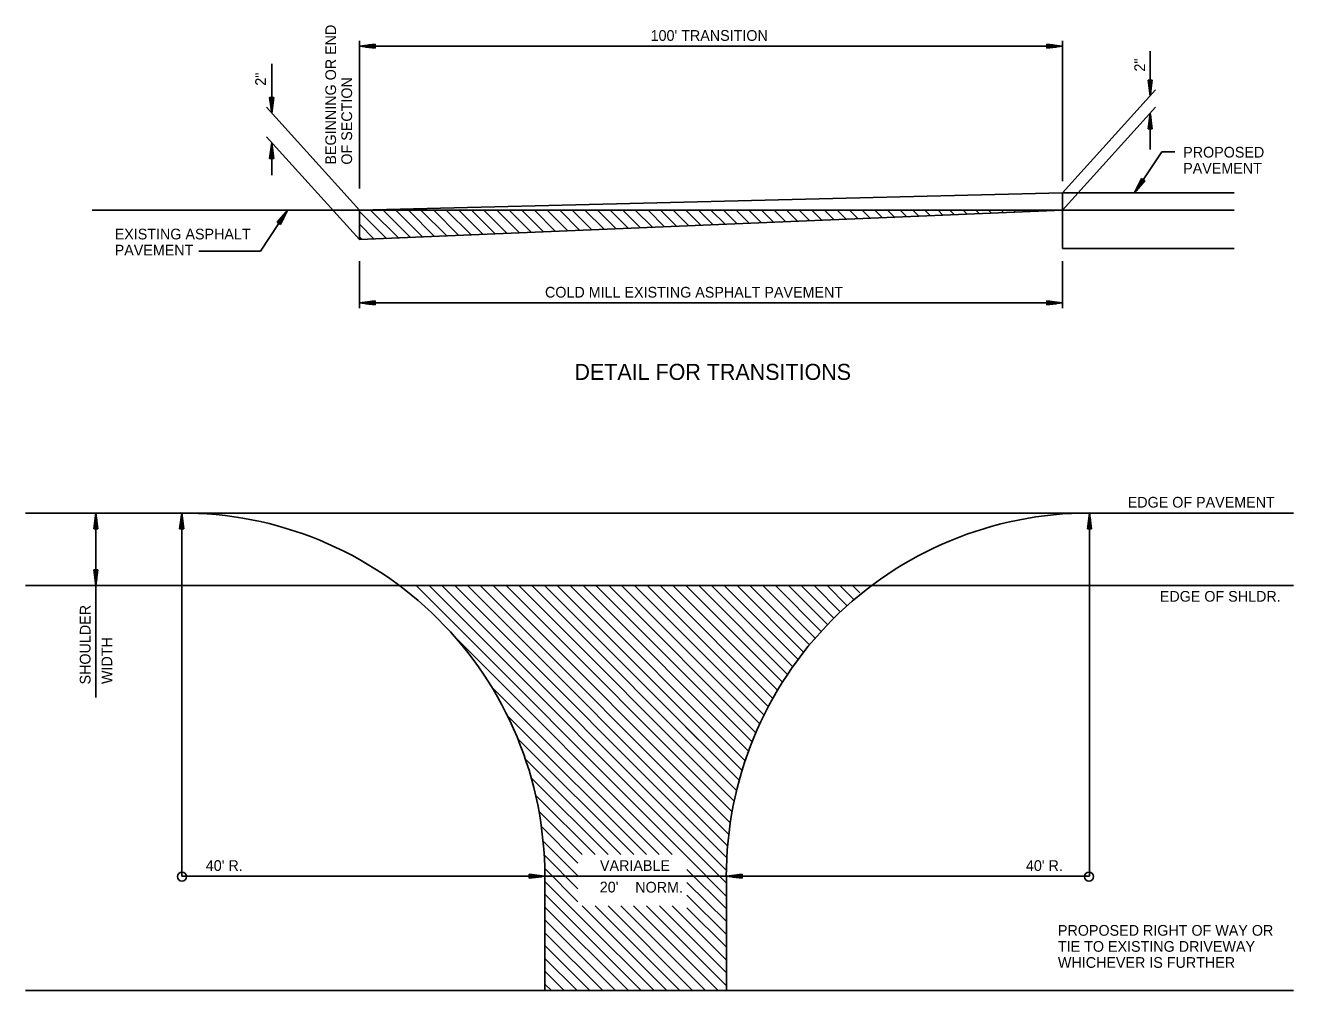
# Model space of a CAD drawing. Extents: x 836 to 5683, y -463 to 1545.
# Drawn here: x 836 to 1548, y 733 to 1274 of the extents above; entities that cross this region are included whole.
import ezdxf

# ---------------------------------------------------------------- set-up
doc = ezdxf.new("R2010")
doc.units = 0
for name, color, linetype in [('R_Border', 7, 'Continuous'), ('R_Draft', 7, 'Continuous'), ('R_Grid', 7, 'Continuous'), ('STAMP_PP', 7, 'Continuous')]:
    doc.layers.add(name, color=color, linetype=linetype)

msp = doc.modelspace()

# ---------------------------------------------------------------- linework, layer by layer
at = {"layer": 'R_Draft'}
for p, q in [((1039.08, 1154.14), (1023.83, 1169.39)), ((1045.98, 1154.29), (1030.08, 1170.19)), ((1052.43, 1154.93), (1037.08, 1170.19)), ((1059.2, 1155.21), (1044.23, 1170.19)), ((1065.97, 1155.49), (1051.33, 1170.19)), ((1072.78, 1155.78), (1058.28, 1170.19)), ((1079.55, 1156.06), (1065.43, 1170.19)), ((1086.36, 1156.34), (1072.43, 1170.19)), ((1093.13, 1156.63), (1079.58, 1170.19)), ((1099.95, 1156.91), (1086.68, 1170.19)), ((1106.71, 1157.19), (1093.63, 1170.19)), ((1113.49, 1157.48), (1100.78, 1170.19)), ((1120.29, 1157.76), (1107.78, 1170.19)), ((1127.07, 1158.04), (1114.93, 1170.19)), ((1133.84, 1158.33), (1122.03, 1170.19)), ((1140.65, 1158.61), (1129.08, 1170.19)), ((1147.42, 1158.89), (1136.13, 1170.19)), ((1154.22, 1159.18), (1143.13, 1170.19)), ((1161, 1159.46), (1150.28, 1170.19)), ((1167.78, 1159.74), (1157.38, 1170.19)), ((1174.59, 1160.03), (1164.43, 1170.19)), ((1181.4, 1160.31), (1171.53, 1170.19)), ((1188.15, 1160.59), (1178.48, 1170.19)), ((1194.94, 1160.88), (1185.63, 1170.19)), ((1201.69, 1161.16), (1192.63, 1170.19)), ((1208.52, 1161.44), (1199.78, 1170.19)), ((1215.34, 1161.73), (1206.88, 1170.19)), ((1222.1, 1162.01), (1213.93, 1170.19)), ((1228.84, 1162.29), (1220.88, 1170.19)), ((1235.61, 1162.57), (1227.93, 1170.19)), ((1242.45, 1162.86), (1235.13, 1170.19)), ((1249.27, 1163.14), (1242.23, 1170.19)), ((1256.04, 1163.42), (1249.28, 1170.19)), ((1262.85, 1163.71), (1256.38, 1170.19)), ((1269.5, 1163.99), (1263.28, 1170.19)), ((1276.39, 1164.27), (1270.48, 1170.19)), ((1283.2, 1164.56), (1277.58, 1170.19)), ((1289.97, 1164.84), (1284.63, 1170.19)), ((1296.79, 1165.12), (1291.73, 1170.19)), ((1303.41, 1165.4), (1298.58, 1170.19)), ((1310.22, 1165.69), (1305.68, 1170.19)), ((1317.14, 1165.97), (1312.93, 1170.19)), ((1323.9, 1166.26), (1319.98, 1170.19)), ((1330.72, 1166.54), (1327.08, 1170.19)), ((1337.49, 1166.82), (1334.13, 1170.19)), ((1344.04, 1167.1), (1340.88, 1170.19)), ((1351.07, 1167.39), (1348.28, 1170.19)), ((1357.53, 1167.66), (1354.93, 1170.19)), ((1364.65, 1167.96), (1362.43, 1170.19)), ((1371.42, 1168.24), (1369.48, 1170.19)), ((1378.24, 1168.52), (1376.58, 1170.19)), ((1385.01, 1168.81), (1383.63, 1170.19)), ((1391.78, 1169.09), (1390.68, 1170.19)), ((1398.59, 1169.37), (1397.78, 1170.19)), ((1405.21, 1169.65), (1404.68, 1170.19)), ((1411.89, 1169.93), (1411.63, 1170.19)), ((1032.13, 1153.99), (1023.83, 1162.29)), ((1025.33, 1153.74), (1023.83, 1155.24))]:
    msp.add_line(p, q, dxfattribs=at)
for points in [[(1055.65, 959.67), (1206.3, 808.85)], [(1062.83, 959.67), (1229.61, 792.78)], [(1070.07, 959.67), (1229.61, 799.96)], [(1077.2, 959.67), (1229.84, 807.03)], [(1084.43, 959.67), (1230.24, 813.76)], [(1091.56, 959.67), (1230.87, 820.25)], [(1098.74, 959.67), (1231.78, 826.69)], [(1106.04, 959.67), (1232.81, 832.85)], [(1113.16, 959.67), (1234, 838.89)], [(1120.4, 959.67), (1235.31, 844.76)], [(1127.58, 959.67), (1236.74, 850.52)], [(1134.77, 959.67), (1238.39, 856.05)], [(1142, 959.67), (1240.16, 861.52)], [(1149.19, 959.67), (1242.04, 866.88)], [(1156.43, 959.67), (1244.03, 872.07)], [(1163.61, 959.67), (1246.14, 877.14)], [(1170.79, 959.67), (1248.31, 882.1)], [(1178.03, 959.67), (1250.7, 887)], [(1185.21, 959.67), (1253.1, 891.85)], [(1192.45, 959.67), (1255.66, 896.46)], [(1199.63, 959.67), (1258.28, 901.02)], [(1206.76, 959.67), (1261.02, 905.47)], [(1214.05, 959.67), (1263.87, 909.8)], [(1221.23, 959.67), (1266.78, 914.08)], [(1228.42, 959.67), (1269.86, 918.29)], [(1235.6, 959.67), (1272.93, 922.34)], [(1242.78, 959.67), (1276.13, 926.39)], [(1249.96, 959.67), (1279.43, 930.26)], [(1257.2, 959.67), (1282.79, 934.03)], [(1264.44, 959.67), (1286.44, 937.67)], [(1271.62, 959.67), (1290.03, 941.26)], [(1278.8, 959.67), (1293.62, 944.86)], [(1286.04, 959.67), (1297.22, 948.45)], [(1293.23, 959.67), (1300.81, 952.04)], [(1078.51, 929.58), (1199.23, 808.85)], [(1097.89, 903.02), (1191.94, 808.85)], [(1106.66, 886.94), (1184.75, 808.85)], [(1206.7, 880.56), (1214.17, 873.09)], [(1112.59, 873.83), (1177.63, 808.85)], [(1206.7, 873.32), (1206.93, 873.09)], [(1116.92, 862.38), (1170.39, 808.85)], [(1120.17, 851.89), (1163.21, 808.85)], [(1122.62, 842.2), (1156.03, 808.85)], [(1124.45, 833.19), (1148.79, 808.85)], [(1125.82, 824.59), (1146.34, 804.07)], [(1126.79, 816.43), (1146.34, 796.88)], [(1127.75, 808.28), (1146.34, 789.64)], [(1206.3, 808.85), (1229.9, 785.26)], [(1127.75, 801.1), (1146.34, 782.46)], [(1207.5, 800.53), (1229.61, 778.47)], [(1127.75, 793.86), (1148.96, 772.66)], [(1207.5, 793.29), (1229.61, 771.29)], [(1127.75, 786.68), (1181.85, 732.59)], [(1207.5, 786.17), (1229.61, 764.11)], [(1127.75, 779.44), (1174.67, 732.59)], [(1148.79, 780.07), (1196.27, 732.59)], [(1155.97, 780.07), (1203.45, 732.59)], [(1163.27, 780.07), (1210.63, 732.59)], [(1170.39, 780.07), (1217.87, 732.59)], [(1177.52, 780.07), (1225, 732.59)], [(1184.81, 780.07), (1229.61, 735.27)], [(1191.99, 780.07), (1229.61, 742.51)], [(1199.18, 780.07), (1229.61, 749.69)], [(1207.5, 778.93), (1229.61, 756.87)], [(1127.75, 772.32), (1167.43, 732.59)], [(1148.96, 772.66), (1189.03, 732.59)], [(1127.75, 765.08), (1160.3, 732.59)], [(1127.75, 757.9), (1153.06, 732.59)], [(1127.75, 750.66), (1145.82, 732.59)], [(1127.75, 743.47), (1138.64, 732.59)], [(1127.75, 736.29), (1131.46, 732.59)]]:
    msp.add_lwpolyline(points, dxfattribs=at)
at = {"layer": 'R_Grid'}
for p, q in [((1023.83, 1182.34), (1023.83, 1265.14)), ((1032.65, 1263.28), (1023.83, 1262.14)), ((1023.83, 1262.14), (1418.08, 1262.14)), ((1023.83, 1262.14), (1032.65, 1262.14)), ((1032.65, 1260.99), (1023.83, 1262.14)), ((1032.65, 1262.36), (1025.62, 1262.36)), ((1032.65, 1261.92), (1025.62, 1261.91)), ((1032.65, 1262.59), (1027.35, 1262.59)), ((1032.66, 1261.68), (1027.35, 1261.68)), ((1032.64, 1262.83), (1029.13, 1262.82)), ((1032.65, 1261.45), (1029.13, 1261.45)), ((1032.65, 1263.06), (1030.91, 1263.05)), ((1032.65, 1261.22), (1030.92, 1261.22)), ((1032.65, 1263.28), (1032.65, 1260.99)), ((1409.25, 1263.28), (1418.08, 1262.14)), ((1409.25, 1260.99), (1409.25, 1263.28)), ((1409.25, 1263.05), (1410.98, 1263.05)), ((1409.25, 1262.82), (1412.77, 1262.82)), ((1409.25, 1262.59), (1414.55, 1262.59)), ((1409.25, 1262.36), (1416.28, 1262.36)), ((1418.08, 1262.14), (1409.25, 1262.14)), ((1409.25, 1260.99), (1418.08, 1262.14)), ((1409.25, 1261.68), (1414.56, 1261.68)), ((1409.25, 1261.21), (1410.99, 1261.22)), ((1409.26, 1261.91), (1416.29, 1261.91)), ((1409.26, 1261.44), (1412.77, 1261.45)), ((1418.08, 1186.39), (1418.08, 1265.14)), ((1467.33, 1234.29), (1467.33, 1259.31)), ((974.58, 1224.59), (974.58, 1252.19)), ((1466.18, 1243.11), (1467.33, 1234.29)), ((1466.18, 1243.11), (1468.47, 1243.11)), ((1466.41, 1243.11), (1466.41, 1241.37)), ((1466.63, 1243.1), (1466.64, 1239.59)), ((1466.87, 1243.11), (1466.87, 1237.81)), ((1467.1, 1243.11), (1467.1, 1236.08)), ((1467.33, 1234.29), (1467.33, 1243.11)), ((1468.47, 1243.11), (1467.33, 1234.29)), ((1467.55, 1243.11), (1467.55, 1236.08)), ((1467.78, 1243.11), (1467.78, 1237.81)), ((1468.01, 1243.11), (1468.02, 1239.59)), ((1468.24, 1243.11), (1468.25, 1241.38)), ((973.43, 1233.41), (974.58, 1224.59)), ((973.43, 1233.41), (975.72, 1233.41)), ((973.66, 1233.41), (973.66, 1231.67)), ((973.89, 1233.4), (973.89, 1229.89)), ((974.12, 1233.41), (974.12, 1228.11)), ((974.35, 1233.41), (974.35, 1226.38)), ((974.58, 1224.59), (974.58, 1233.41)), ((975.72, 1233.41), (974.58, 1224.59)), ((974.8, 1233.41), (974.8, 1226.38)), ((975.03, 1233.41), (975.03, 1228.11)), ((975.26, 1233.41), (975.27, 1229.89)), ((975.49, 1233.41), (975.5, 1231.68)), ((1418.08, 1179.89), (1470.33, 1237.61)), ((1023.83, 1170.19), (971.58, 1227.91)), ((1418.08, 1170.19), (1470.33, 1227.86)), ((1466.18, 1215.82), (1467.33, 1224.65)), ((1467.33, 1204.27), (1467.33, 1224.65)), ((1467.33, 1224.65), (1467.33, 1215.82)), ((1468.47, 1215.82), (1467.33, 1224.65)), ((1466.41, 1215.82), (1466.41, 1217.55)), ((1466.64, 1215.82), (1466.64, 1219.34)), ((1466.87, 1215.82), (1466.87, 1221.12)), ((1467.11, 1215.82), (1467.1, 1222.85)), ((1467.55, 1215.83), (1467.55, 1222.86)), ((1467.78, 1215.82), (1467.78, 1221.13)), ((1468.02, 1215.83), (1468.01, 1219.34)), ((1468.25, 1215.82), (1468.24, 1217.56)), ((1023.83, 1153.74), (971.58, 1211.41)), ((1468.47, 1215.82), (1466.18, 1215.82)), ((973.44, 1199.26), (974.58, 1208.09)), ((973.89, 1199.26), (973.89, 1202.78)), ((974.12, 1199.26), (974.12, 1204.56)), ((974.36, 1199.26), (974.35, 1206.29)), ((974.58, 1189.79), (974.58, 1208.09)), ((974.58, 1208.09), (974.58, 1199.26)), ((975.73, 1199.26), (974.58, 1208.09)), ((974.81, 1199.27), (974.8, 1206.3)), ((975.03, 1199.26), (975.03, 1204.57)), ((975.27, 1199.27), (975.26, 1202.78)), ((1458.53, 1179.89), (1473.73, 1202.94)), ((1473.73, 1202.94), (1481.03, 1202.94)), ((975.73, 1199.26), (973.44, 1199.26)), ((973.66, 1199.26), (973.66, 1200.99)), ((975.5, 1199.26), (975.49, 1201)), ((1462.43, 1187.88), (1458.53, 1179.89)), ((1462.43, 1187.88), (1464.34, 1186.62)), ((1458.53, 1179.89), (1463.39, 1187.25)), ((1464.34, 1186.62), (1458.53, 1179.89)), ((1463.19, 1187.37), (1459.32, 1181.51)), ((1463.57, 1187.13), (1459.7, 1181.26)), ((1463.01, 1187.51), (1460.09, 1183.07)), ((1463.77, 1187), (1460.85, 1182.58)), ((1462.81, 1187.63), (1460.87, 1184.69)), ((1462.62, 1187.76), (1461.67, 1186.3)), ((1463.96, 1186.88), (1462.03, 1183.94)), ((1464.15, 1186.75), (1463.2, 1185.3)), ((983.48, 1170.19), (968.28, 1147.14)), ((977.67, 1163.45), (983.48, 1170.19)), ((978.23, 1163.07), (981.16, 1167.49)), ((978.43, 1162.94), (982.3, 1168.81)), ((983.48, 1170.19), (978.62, 1162.82)), ((978.81, 1162.7), (982.68, 1168.57)), ((979, 1162.57), (981.92, 1167)), ((979.58, 1162.19), (983.48, 1170.19)), ((979.58, 1162.19), (977.67, 1163.45)), ((977.85, 1163.32), (978.8, 1164.77)), ((978.05, 1163.19), (979.98, 1166.14)), ((979.2, 1162.44), (981.13, 1165.38)), ((979.39, 1162.31), (980.34, 1163.77)), ((968.28, 1147.14), (933.74, 1147.14)), ((1023.83, 1141.59), (1023.83, 1115.19)), ((1418.08, 1141.59), (1418.08, 1115.19)), ((1032.65, 1119.33), (1023.83, 1118.19)), ((1023.83, 1118.19), (1418.08, 1118.19)), ((1023.83, 1118.19), (1032.65, 1118.19)), ((1032.65, 1117.04), (1023.83, 1118.19)), ((1032.65, 1118.41), (1025.62, 1118.41)), ((1032.65, 1117.97), (1025.62, 1117.96)), ((1032.65, 1118.64), (1027.35, 1118.64)), ((1032.66, 1117.73), (1027.35, 1117.73)), ((1032.64, 1118.88), (1029.13, 1118.87)), ((1032.65, 1117.5), (1029.13, 1117.5)), ((1032.65, 1119.11), (1030.91, 1119.1)), ((1032.65, 1117.27), (1030.92, 1117.27)), ((1032.65, 1119.33), (1032.65, 1117.04)), ((1409.25, 1119.33), (1418.08, 1118.19)), ((1409.25, 1117.04), (1409.25, 1119.33)), ((1409.25, 1119.1), (1410.98, 1119.11)), ((1409.25, 1118.87), (1412.77, 1118.88)), ((1409.25, 1118.64), (1414.55, 1118.64)), ((1409.25, 1118.41), (1416.28, 1118.41)), ((1418.08, 1118.19), (1409.25, 1118.19)), ((1409.25, 1117.04), (1418.08, 1118.19)), ((1409.25, 1117.73), (1414.56, 1117.73)), ((1409.25, 1117.27), (1410.99, 1117.27)), ((1409.26, 1117.96), (1416.29, 1117.96)), ((1409.26, 1117.49), (1412.77, 1117.5)), ((874.84, 991.55), (875.98, 1000.37)), ((875.52, 991.54), (875.52, 996.85)), ((875.76, 991.55), (875.75, 998.58)), ((875.98, 959.67), (875.98, 1000.37)), ((875.98, 1000.37), (875.98, 991.55)), ((877.12, 991.55), (875.98, 1000.37)), ((876.2, 991.55), (876.2, 998.58)), ((876.43, 991.55), (876.43, 996.85)), ((922.95, 991.55), (924.09, 1000.37)), ((923.64, 991.54), (923.64, 996.85)), ((923.87, 991.55), (923.87, 998.58)), ((924.09, 1000.37), (924.09, 796.71)), ((924.09, 1000.37), (924.09, 991.55)), ((925.24, 991.55), (924.09, 1000.37)), ((924.32, 991.55), (924.32, 998.58)), ((924.55, 991.55), (924.55, 996.85)), ((1432.13, 991.55), (1433.27, 1000.37)), ((1432.82, 991.54), (1432.82, 996.85)), ((1433.05, 991.55), (1433.05, 998.58)), ((1433.27, 1000.37), (1433.27, 796.71)), ((1433.27, 1000.37), (1433.27, 991.55)), ((1434.42, 991.55), (1433.27, 1000.37)), ((1433.5, 991.55), (1433.5, 998.58)), ((1433.73, 991.55), (1433.73, 996.85)), ((877.12, 991.55), (874.84, 991.55)), ((875.06, 991.55), (875.06, 993.28)), ((875.29, 991.55), (875.29, 995.07)), ((876.67, 991.55), (876.66, 995.07)), ((876.9, 991.55), (876.89, 993.29)), ((925.24, 991.55), (922.95, 991.55)), ((923.18, 991.55), (923.17, 993.28)), ((923.41, 991.55), (923.4, 995.07)), ((924.78, 991.55), (924.78, 995.07)), ((925.01, 991.55), (925.01, 993.29)), ((1434.42, 991.55), (1432.13, 991.55)), ((1432.36, 991.55), (1432.35, 993.28)), ((1432.59, 991.55), (1432.58, 995.07)), ((1433.96, 991.55), (1433.96, 995.07)), ((1434.19, 991.55), (1434.19, 993.29)), ((874.83, 968.5), (875.98, 959.67)), ((874.83, 968.5), (877.12, 968.5)), ((875.06, 968.5), (875.06, 966.76)), ((875.28, 968.49), (875.29, 964.98)), ((875.52, 968.5), (875.52, 963.2)), ((875.75, 968.5), (875.75, 961.47)), ((875.98, 959.67), (875.98, 968.5)), ((877.12, 968.5), (875.98, 959.67)), ((876.2, 968.5), (876.2, 961.47)), ((876.43, 968.5), (876.43, 963.2)), ((876.66, 968.5), (876.67, 964.98)), ((876.89, 968.5), (876.9, 966.77)), ((875.98, 896.92), (875.98, 959.67)), ((924.09, 796.71), (1127.75, 796.71)), ((1118.93, 797.85), (1127.75, 796.71)), ((1118.93, 795.56), (1118.93, 797.85)), ((1118.93, 797.63), (1120.66, 797.63)), ((1118.93, 797.39), (1122.45, 797.4)), ((1118.93, 797.17), (1124.23, 797.17)), ((1118.93, 796.93), (1125.96, 796.94)), ((1127.75, 796.71), (1118.93, 796.71)), ((1118.93, 795.56), (1127.75, 796.71)), ((1127.75, 796.71), (1229.61, 796.71)), ((1238.43, 797.86), (1229.61, 796.71)), ((1229.61, 796.71), (1433.27, 796.71)), ((1229.61, 796.71), (1238.44, 796.71)), ((1238.44, 795.57), (1229.61, 796.71)), ((1238.43, 796.94), (1231.4, 796.94)), ((1238.44, 797.17), (1233.13, 797.16)), ((1238.43, 797.4), (1234.91, 797.4)), ((1238.44, 797.63), (1236.7, 797.62)), ((1238.43, 797.86), (1238.44, 795.57)), ((1118.93, 796.48), (1125.96, 796.48)), ((1118.93, 796.25), (1124.23, 796.26)), ((1118.93, 795.79), (1120.67, 795.8)), ((1118.94, 796.02), (1122.45, 796.02)), ((1238.44, 796.49), (1231.4, 796.49)), ((1238.44, 796.25), (1233.14, 796.26)), ((1238.44, 796.03), (1234.92, 796.02)), ((1238.44, 795.8), (1236.71, 795.79))]:
    msp.add_line(p, q, dxfattribs=at)
for centre in [(924.31, 796.52), (1432.97, 796.49)]:
    msp.add_circle(centre, 2.55, dxfattribs=at)
at = {"layer": 'STAMP_PP'}
for p, q in [((1418.08, 1179.89), (1023.83, 1170.19)), ((1514.33, 1179.89), (1418.08, 1179.89)), ((1418.08, 1179.89), (1418.08, 1170.19)), ((873.83, 1170.19), (1023.78, 1170.19)), ((1023.83, 1170.19), (1023.83, 1153.74)), ((1418.08, 1170.19), (1023.83, 1170.19)), ((1418.08, 1170.19), (1023.83, 1153.74)), ((1418.08, 1170.19), (1418.08, 1148.74)), ((1514.33, 1170.19), (1418.08, 1170.19)), ((1514.33, 1148.74), (1418.08, 1148.74)), ((836.43, 1000.37), (1547.73, 1000.37)), ((836.43, 959.67), (1547.73, 959.67)), ((1127.75, 796.71), (1127.75, 732.59)), ((1229.61, 732.59), (1229.61, 796.71)), ((836.43, 732.59), (1547.73, 732.59))]:
    msp.add_line(p, q, dxfattribs=at)
for points in [[(1300.41, 959.67), (1304.4, 955.68)], [(1307.65, 959.67), (1308.05, 959.28)]]:
    msp.add_lwpolyline(points, dxfattribs=at)
for centre, start, end in [((924.08, 796.75), 0, 90.21548), ((1433.21, 796.75), 89.99893, 180.10383)]:
    msp.add_arc(centre, 203.66, start, end, dxfattribs=at)

# ---------------------------------------------------------------- texts
at = {"layer": 'R_Border'}
for s, p in [('BEGINNING OR END', (1010.67, 1195.74)), ('2"', (1464.4, 1247.92)), ('2"', (971.33, 1239.99)), ('OF SECTION', (1019.67, 1195.74)), ('SHOULDER', (872.97, 904.26)), ('WIDTH', (885.16, 904.51))]:
    msp.add_text(s, height=6, rotation=90, dxfattribs=at).set_placement(p)
for s, height, p in [("100' TRANSITION", 6, (1187.1, 1265.14)), ('PROPOSED', 6, (1485.78, 1199.7)), ('PAVEMENT', 6, (1485.78, 1190.7)), ('EXISTING ASPHALT', 6, (886.52, 1153.81)), ('PAVEMENT', 6, (886.52, 1144.81)), ('COLD MILL EXISTING ASPHALT PAVEMENT', 6, (1127.86, 1121.19)), (' DETAIL FOR TRANSITIONS ', 9, (1141.03, 1075.02)), (' EDGE OF PAVEMENT', 6, (1452.44, 1003.43)), (' EDGE OF SHLDR.', 6, (1470.46, 950.67)), ("40' R.", 6, (937.62, 799.72)), ('VARIABLE', 6, (1158.7, 799.71)), ("40' R.", 6, (1397.59, 799.69)), ("20'", 6, (1158.58, 787.65)), ('NORM.', 6, (1178.47, 787.56)), ('PROPOSED RIGHT OF WAY OR', 6, (1415.53, 763.37)), ('TIE TO EXISTING DRIVEWAY', 6, (1415.53, 754.37)), ('WHICHEVER IS FURTHER', 6, (1415.53, 745.37))]:
    msp.add_text(s, height=height, dxfattribs=at).set_placement(p)

doc.saveas('drawing.dxf')
